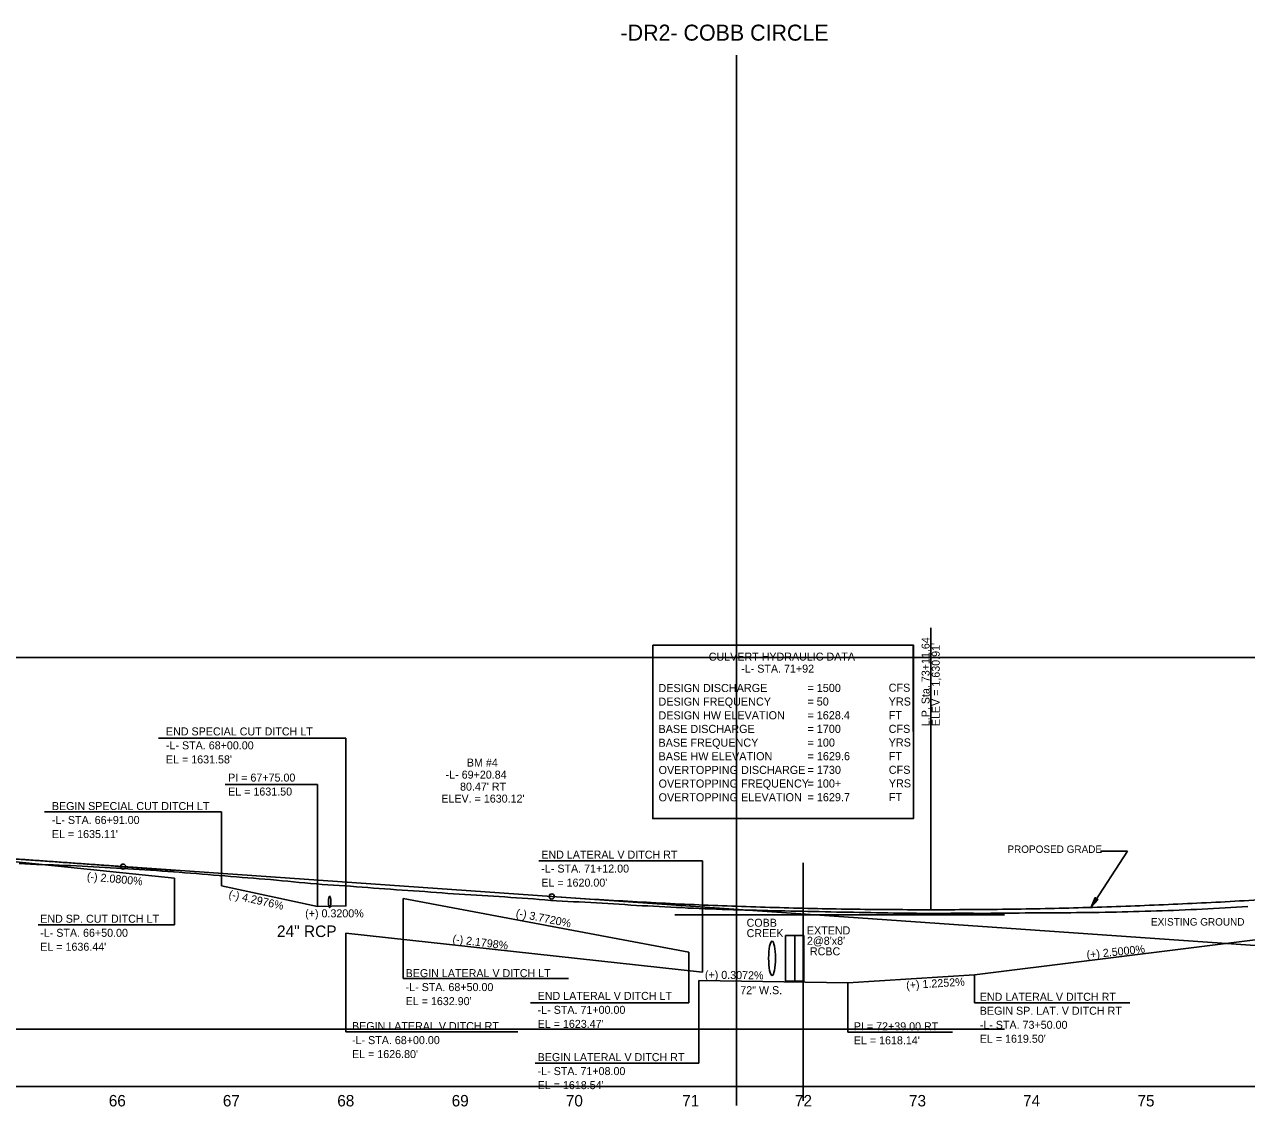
# Model space of a CAD drawing. Extents: x 498575 to 532350, y 405181 to 484585.
# Drawn here: x 511338 to 512407, y 483216 to 484163 of the extents above; entities that cross this region are included whole.
import ezdxf

# ---------------------------------------------------------------- set-up
doc = ezdxf.new("R2010")
doc.units = 0
for name, color, linetype in [('Default', 7, 'Continuous'), ('Exist Profile Cell', 7, 'Continuous'), ('Exist Structure Major Box Culvert or Tunnel Topo', 7, 'Continuous'), ('Exist Vertical Profile Ground Line', 7, 'Continuous'), ('Exist Vertical Profile Horizontal Axis Label Major', 7, 'Continuous'), ('Prop Drainage Structure Pipe RCP 60in Class III', 7, 'Continuous'), ('Prop Drainage Structure Pipe Welded Steel 54in Label', 7, 'Continuous'), ('Prop Grid Mask', 7, 'Continuous'), ('Prop PFL Text', 7, 'Continuous'), ('Prop Vertical Profile Curve Label', 7, 'Continuous'), ('Prop Vertical Profile Ditch Grade Left', 7, 'Continuous'), ('Prop Vertical Profile Ditch Grade Left Label', 7, 'Continuous'), ('Prop Vertical Profile Ditch Grade Right', 7, 'Continuous'), ('Prop Vertical Profile Ditch Grade Right Label', 7, 'Continuous'), ('Prop Vertical Profile Grade', 7, 'Continuous'), ('Prop Vertical Profile Strip Grade', 7, 'Continuous'), ('Prop VPI Label', 7, 'Continuous'), ('Scratch_Level_2', 7, 'Continuous'), ('Scratch_Level_4', 7, 'Continuous'), ('Scratch_Level_5', 7, 'Continuous'), ('Scratch_Level_8', 7, 'Continuous')]:
    doc.layers.add(name, color=color, linetype=linetype)

msp = doc.modelspace()

# ---------------------------------------------------------------- linework, layer by layer
at = {"layer": 'Exist Profile Cell'}
msp.add_line((505856.7, 483233.7), (526056.7, 483233.7), dxfattribs=at)
at = {"layer": 'Exist Structure Major Box Culvert or Tunnel Topo'}
for p, q in [((512003.7, 483325.7), (512003.7, 483365.7)), ((512011.7, 483325.7), (512011.7, 483365.7)), ((512019.7, 483325.7), (512019.7, 483365.7)), ((512003.7, 483325.7), (512011.7, 483325.7)), ((512011.7, 483325.7), (512019.7, 483325.7))]:
    msp.add_line(p, q, dxfattribs=at)
msp.add_lwpolyline([(512003.7, 483365.7), (512019.7, 483365.7)], dxfattribs=at)
at = {"layer": 'Exist Vertical Profile Ground Line'}
for points in [[(511333.2, 483428.7), (511338.2, 483428.4), (511343.2, 483428.2), (511348.2, 483427.9), (511353.2, 483427.8), (511358.2, 483427.6), (511363.2, 483427.5), (511368.2, 483427.3), (511373.2, 483427.1), (511378.2, 483426.9), (511383.2, 483426.6), (511388.2, 483426.4), (511393.2, 483426.1), (511398.2, 483425.8), (511403.2, 483425.6), (511408.2, 483425.3), (511413.2, 483425), (511418.2, 483424.7), (511423.2, 483424.4), (511428.2, 483424.1), (511433.2, 483423.8), (511438.2, 483423.5), (511443.2, 483423.2), (511448.2, 483422.8), (511453.2, 483422.5), (511458.2, 483422.1), (511463.2, 483421.7), (511468.2, 483421.4), (511473.2, 483421.1), (511478.2, 483420.7), (511483.2, 483420.3), (511488.2, 483419.9), (511493.2, 483419.4), (511498.2, 483419), (511503.2, 483418.6), (511508.2, 483418.2), (511513.2, 483417.8), (511518.2, 483417.4), (511523.2, 483417), (511528.2, 483416.6), (511533.2, 483416.2), (511538.2, 483415.8), (511543.2, 483415.4), (511548.2, 483415), (511553.2, 483414.6), (511558.2, 483414.2), (511563.2, 483413.7), (511568.2, 483413.2), (511573.2, 483412.7), (511578.2, 483412.2), (511583.2, 483411.7), (511588.2, 483411.3), (511593.2, 483410.9), (511598.2, 483410.5), (511603.2, 483410.1), (511608.2, 483409.8), (511613.2, 483409.5), (511618.2, 483409.1), (511623.2, 483408.8), (511628.2, 483408.4), (511633.2, 483408), (511638.2, 483407.6), (511643.2, 483407.2), (511648.2, 483406.9), (511653.2, 483406.5), (511658.2, 483406.2), (511663.2, 483405.8), (511668.2, 483405.5), (511673.2, 483405.1), (511678.2, 483404.8), (511683.2, 483404.5), (511688.2, 483404.1), (511693.2, 483403.8), (511698.2, 483403.4), (511703.2, 483403), (511708.2, 483402.6), (511713.2, 483402.3), (511718.2, 483402), (511723.2, 483401.7), (511728.2, 483401.4), (511733.2, 483401.1), (511738.2, 483400.8), (511743.2, 483400.5), (511748.2, 483400.1), (511753.2, 483399.8), (511758.2, 483399.5), (511763.2, 483399.1), (511768.2, 483398.8), (511773.2, 483398.4), (511778.2, 483398), (511783.2, 483397.7), (511788.2, 483397.3), (511793.2, 483396.9), (511798.2, 483396.5), (511803.2, 483396.2), (511808.2, 483395.9), (511813.2, 483395.6)], [(511813.2, 483395.6), (511818.2, 483395.3), (511823.2, 483395.1), (511828.2, 483394.9), (511833.2, 483394.6), (511838.2, 483394.3), (511843.2, 483394), (511848.2, 483393.7), (511853.2, 483393.4), (511858.2, 483393.1), (511863.2, 483392.8), (511868.2, 483392.4), (511873.2, 483392.1), (511878.2, 483391.8), (511883.2, 483391.6), (511888.2, 483391.3), (511893.2, 483391.1), (511898.2, 483390.8), (511903.2, 483390.6), (511908.2, 483390.3), (511913.2, 483390.1), (511918.2, 483389.8), (511923.2, 483389.6), (511928.2, 483389.4), (511933.2, 483389.2), (511938.2, 483389), (511943.2, 483388.8), (511948.2, 483388.6), (511953.2, 483388.4), (511958.2, 483388.3), (511963.2, 483388.2), (511968.2, 483388), (511973.2, 483387.9), (511978.2, 483387.8), (511983.2, 483387.7), (511988.2, 483387.5), (511993.2, 483387.4), (511998.2, 483387.3), (512003.2, 483387.2), (512008.2, 483387.1), (512013.2, 483387), (512018.2, 483386.9), (512023.2, 483386.8), (512028.2, 483386.7), (512033.2, 483386.6), (512038.2, 483386.5), (512043.2, 483386.4), (512048.2, 483386.3), (512053.2, 483386.3), (512058.2, 483386.2), (512063.2, 483386.1), (512068.2, 483386), (512073.2, 483385.9), (512078.2, 483385.8), (512083.2, 483385.7), (512088.2, 483385.6), (512093.2, 483385.5), (512098.2, 483385.4), (512103.2, 483385.4), (512108.2, 483385.3), (512113.2, 483385.2), (512118.2, 483385.2), (512123.2, 483385.1), (512128.2, 483385.1), (512133.2, 483385.1), (512138.2, 483385.1), (512143.2, 483385.1), (512148.2, 483385.2), (512153.2, 483385.2), (512158.2, 483385.2), (512163.2, 483385.2), (512168.2, 483385.2), (512173.2, 483385.1), (512178.2, 483385.1), (512183.2, 483385.2), (512188.2, 483385.2), (512193.2, 483385.2), (512198.2, 483385.2), (512203.2, 483385.4), (512208.2, 483385.4), (512213.2, 483385.5), (512218.2, 483385.5), (512223.2, 483385.6), (512228.2, 483385.6), (512233.2, 483385.7), (512238.2, 483385.7), (512243.2, 483385.7), (512248.2, 483385.7), (512253.2, 483385.7), (512258.2, 483385.8), (512263.2, 483385.8), (512268.2, 483385.9), (512273.2, 483385.9), (512278.2, 483386), (512283.2, 483386.1), (512288.2, 483386.2), (512293.2, 483386.3), (512298.2, 483386.4), (512303.2, 483386.5), (512308.2, 483386.7), (512313.2, 483386.8)], [(512313.2, 483386.8), (512318.2, 483387), (512323.2, 483387.1), (512328.2, 483387.3), (512333.2, 483387.4), (512338.2, 483387.6), (512343.2, 483387.7), (512348.2, 483387.9), (512353.2, 483388.1), (512358.2, 483388.4), (512363.2, 483388.6), (512368.2, 483388.8), (512373.2, 483389.1), (512378.2, 483389.4), (512383.2, 483389.7), (512388.2, 483390), (512393.2, 483390.3), (512398.2, 483390.6), (512403.2, 483390.9), (512408.2, 483391.1)]]:
    msp.add_lwpolyline(points, dxfattribs=at)
at = {"layer": 'Prop Drainage Structure Pipe RCP 60in Class III'}
msp.add_ellipse((511991.9, 483345.8), major_axis=(0, 15), ratio=0.2, dxfattribs=at)
at = {"layer": 'Prop Drainage Structure Pipe Welded Steel 54in Label'}
msp.add_ellipse((511604.8, 483395.2), major_axis=(0, 5), ratio=0.2, dxfattribs=at)
at = {"layer": 'Prop Grid Mask'}
for points in [[(511887.6, 483619.9), (512115.5, 483619.9), (512115.5, 483468), (511887.6, 483468)], [(511887.7, 483467.9), (512115.5, 483468), (512115.4, 483619.9), (511887.6, 483619.7)]]:
    msp.add_lwpolyline(points, close=True, dxfattribs=at)
at = {"layer": 'Prop PFL Text'}
for p, q in [((512271.2, 483390.4), (512302.8, 483439.5)), ((512302.8, 483439.5), (512279.3, 483439.5))]:
    msp.add_line(p, q, dxfattribs=at)
msp.add_lwpolyline([(512277.3, 483397.1), (512271.2, 483390.4), (512274.7, 483398.9), (512275.4, 483397)], close=True, dxfattribs=at)
at = {"layer": 'Prop Vertical Profile Curve Label'}
for centre in [(511424.1, 483426), (511799.1, 483399.9)]:
    msp.add_circle(centre, 2.25, dxfattribs=at)
at = {"layer": 'Prop Vertical Profile Ditch Grade Left'}
for points in [[(511169.1, 483437.2), (511319.1, 483431.5), (511469.1, 483415.9), (511469.1, 483415.9)], [(511510.1, 483409.3), (511594.1, 483391.2), (511619.1, 483391.6), (511619.1, 483391.6)], [(511669.1, 483398.2), (511919.1, 483351.1), (511919.1, 483351.1)]]:
    msp.add_lwpolyline(points, dxfattribs=at)
at = {"layer": 'Prop Vertical Profile Ditch Grade Left Label'}
for p, q in [((511455.2, 483538.3), (511619.1, 483538.3)), ((511619.1, 483538.3), (511619.1, 483391.6)), ((511513.4, 483497.9), (511594.1, 483497.9)), ((511594.1, 483497.9), (511594.1, 483391.2)), ((511355.3, 483473.9), (511510.1, 483473.9)), ((511510.1, 483473.9), (511510.1, 483409.3)), ((511469.1, 483415.9), (511469.1, 483375)), ((511669.1, 483398.2), (511669.1, 483328)), ((511349.7, 483375), (511469.1, 483375)), ((511919.1, 483351.1), (511919.1, 483306.9)), ((511669.1, 483328), (511813.9, 483328)), ((511780.4, 483306.9), (511919.1, 483306.9))]:
    msp.add_line(p, q, dxfattribs=at)
at = {"layer": 'Prop Vertical Profile Ditch Grade Right'}
for points in [[(511927.9, 483326.4), (512058.1, 483324.4), (512169.1, 483331.2), (512569.1, 483381.2)], [(511619.1, 483367.7), (511931.1, 483333.7)]]:
    msp.add_lwpolyline(points, dxfattribs=at)
at = {"layer": 'Prop Vertical Profile Ditch Grade Right Label'}
for p, q in [((511931.1, 483431), (511787.9, 483431)), ((511931.1, 483333.7), (511931.1, 483431)), ((511619.1, 483367.7), (511619.1, 483281.4)), ((512169.1, 483331.2), (512169.1, 483306.9)), ((511927.9, 483326.4), (511927.9, 483253.9)), ((512058.1, 483324.4), (512058.1, 483281.2)), ((512304.9, 483306.9), (512169.1, 483306.9)), ((511769.5, 483281.4), (511619.1, 483281.4)), ((512149.7, 483281.2), (512058.1, 483281.2)), ((511927.9, 483253.9), (511784.7, 483253.9))]:
    msp.add_line(p, q, dxfattribs=at)
at = {"layer": 'Prop Vertical Profile Grade'}
msp.add_line((511424.1, 483426), (511799.1, 483399.9), dxfattribs=at)
for points in [[(511799.1, 483399.9), (511832.3, 483397.6), (511865.5, 483395.7), (511898.7, 483393.9), (511931.9, 483392.4), (511965.1, 483391.2), (511998.3, 483390.1), (512031.5, 483389.3), (512064.7, 483388.7), (512097.9, 483388.4), (512131.1, 483388.3), (512164.3, 483388.4), (512197.5, 483388.7), (512230.7, 483389.3), (512263.9, 483390.1), (512297.1, 483391.2), (512330.3, 483392.5), (512363.5, 483394), (512396.7, 483395.7), (512429.9, 483397.7), (512463.1, 483399.9), (512496.3, 483402.3), (512529.5, 483405), (512562.7, 483407.9), (512595.9, 483411), (512629.1, 483414.4), (512662.3, 483418), (512695.5, 483421.8), (512728.7, 483425.9), (512761.9, 483430.2), (512795.1, 483434.7), (512828.3, 483439.5), (512861.5, 483444.5), (512894.7, 483449.7), (512927.9, 483455.2), (512961.1, 483460.8), (512994.3, 483466.8), (513027.5, 483472.9), (513060.7, 483479.3), (513093.9, 483485.9), (513127.1, 483492.8), (513160.3, 483499.8), (513193.5, 483507.1), (513226.7, 483514.7), (513259.9, 483522.5), (513293.1, 483530.5), (513326.3, 483538.7), (513359.5, 483547.2), (513392.7, 483555.9), (513425.9, 483564.8), (513459.1, 483574)], [(510724.1, 483483.2), (510738.1, 483481.9), (510752.1, 483480.6), (510766.1, 483479.3), (510780.1, 483478), (510794.1, 483476.8), (510808.1, 483475.5), (510822.1, 483474.2), (510836.1, 483473), (510850.1, 483471.7), (510864.1, 483470.5), (510878.1, 483469.2), (510892.1, 483468), (510906.1, 483466.8), (510920.1, 483465.5), (510934.1, 483464.3), (510948.1, 483463.1), (510962.1, 483461.9), (510976.1, 483460.7), (510990.1, 483459.5), (511004.1, 483458.4), (511018.1, 483457.2), (511032.1, 483456), (511046.1, 483454.8), (511060.1, 483453.7), (511074.1, 483452.5), (511088.1, 483451.4), (511102.1, 483450.3), (511116.1, 483449.1), (511130.1, 483448), (511144.1, 483446.9), (511158.1, 483445.8), (511172.1, 483444.7), (511186.1, 483443.6), (511200.1, 483442.5), (511214.1, 483441.4), (511228.1, 483440.4), (511242.1, 483439.3), (511256.1, 483438.2), (511270.1, 483437.2), (511284.1, 483436.1), (511298.1, 483435.1), (511312.1, 483434.1), (511326.1, 483433), (511340.1, 483432), (511354.1, 483431), (511368.1, 483430), (511382.1, 483429), (511396.1, 483428), (511410.1, 483427), (511424.1, 483426)]]:
    msp.add_spline(points, degree=3, dxfattribs=at)
at = {"layer": 'Prop Vertical Profile Strip Grade'}
msp.add_line((512130.7, 483635), (512130.7, 483388.3), dxfattribs=at)
at = {"layer": 'Prop VPI Label'}
for p, q in [((511424.1, 483426), (511076.8, 483450.3)), ((511799.1, 483399.9), (512626.3, 483342.1))]:
    msp.add_line(p, q, dxfattribs=at)
at = {"layer": 'Scratch_Level_2'}
msp.add_line((511960.7, 484136), (511960.7, 483216.9), dxfattribs=at)
at = {"layer": 'Scratch_Level_4'}
for p, q in [((512019.1, 483221.2), (512019.1, 483429.2)), ((511906.7, 483383.7), (512195.1, 483383.7)), ((512019.1, 483320.4), (512019.1, 483233.7)), ((505856.7, 483283.7), (512195.1, 483283.7)), ((511906.7, 483233.7), (512195.1, 483233.7))]:
    msp.add_line(p, q, dxfattribs=at)
at = {"layer": 'Scratch_Level_5'}
msp.add_line((513582.6, 483609), (498575.1, 483609), dxfattribs=at)
at = {"layer": 'Scratch_Level_8'}
msp.add_line((511469.1, 483422.6), (511419.1, 483426), dxfattribs=at)

# ---------------------------------------------------------------- texts
at = {"layer": 'Default'}
for s, height, p in [('CULVERT HYDRAULIC DATA', 7, (511936.5, 483606.2)), ('-L- STA. 71+92', 7, (511964.9, 483595.7)), ('DESIGN DISCHARGE', 7.087, (511892.5, 483578.7)), ('DESIGN DISCHARGE', 7.087, (511892.5, 483578.7)), ('= 1500', 7.09, (512022.8, 483578.8)), ('CFS', 7.09, (512093.9, 483579)), ('DESIGN FREQUENCY', 7.087, (511892.5, 483566.8)), ('DESIGN FREQUENCY', 7.087, (511892.5, 483566.8)), ('= 50', 7.09, (512022.8, 483566.9)), ('YRS', 7.09, (512093.9, 483566.9)), ('DESIGN HW ELEVATION', 7.087, (511892.5, 483554.8)), ('DESIGN HW ELEVATION', 7.087, (511892.5, 483554.8)), ('= 1628.4', 7.09, (512022.8, 483554.9)), ('FT', 7.09, (512093.9, 483555)), ('BASE DISCHARGE', 7.087, (511892.5, 483542.9)), ('BASE DISCHARGE', 7.087, (511892.5, 483542.9)), ('= 1700', 7.09, (512022.8, 483543)), ('CFS', 7.09, (512093.9, 483543)), ('BASE FREQUENCY', 7.087, (511892.5, 483530.9)), ('BASE FREQUENCY', 7.087, (511892.5, 483530.9)), ('= 100', 7.09, (512022.9, 483531)), ('YRS', 7.09, (512093.9, 483531.1)), ('BASE HW ELEVATION', 7.087, (511892.6, 483519)), ('BASE HW ELEVATION', 7.087, (511892.6, 483519)), ('= 1629.6', 7.09, (512022.9, 483519.1)), ('FT', 7.09, (512093.9, 483519.1)), ('OVERTOPPING DISCHARGE', 7.087, (511892.6, 483507)), ('= 1730', 7.09, (512022.9, 483507.1)), ('CFS', 7.09, (512094, 483507.2)), ('OVERTOPPING FREQUENCY', 7.087, (511892.6, 483495.1)), ('= 100+', 7.09, (512022.9, 483495.2)), ('YRS', 7.09, (512094, 483495.3)), ('OVERTOPPING ELEVATION', 7.087, (511892.6, 483483.1)), ('= 1629.7', 7.09, (512022.9, 483483.2)), ('FT', 7.09, (512094, 483483.3))]:
    msp.add_text(s, height=height, rotation=0.0449, dxfattribs=at).set_placement(p)
for s, p in [('COBB ', (511969.6, 483373.4)), ('EXTEND', (512022.4, 483366.7)), ('CREEK', (511969.6, 483364.3)), ("2@8'x8' ", (512022.4, 483357.6)), (' RCBC', (512022.4, 483348.4)), ('72" W.S.', (511964.1, 483314.4))]:
    msp.add_text(s, height=7, dxfattribs=at).set_placement(p)
at = {"layer": 'Exist Vertical Profile Horizontal Axis Label Major'}
for s, p in [('66', (511411.6, 483216.2)), ('66', (511411.6, 483216.2)), ('67', (511511.4, 483216.2)), ('67', (511511.4, 483216.2)), ('68', (511611.5, 483216.2)), ('68', (511611.5, 483216.2)), ('69', (511711.6, 483216.2)), ('69', (511711.6, 483216.2)), ('70', (511811.5, 483216.2)), ('70', (511811.5, 483216.2)), ('71', (511913.3, 483216.2)), ('71', (511913.3, 483216.2)), ('72', (512011.9, 483216.2)), ('72', (512011.9, 483216.2)), ('73', (512111.7, 483216.2)), ('73', (512111.7, 483216.2)), ('74', (512211.5, 483216.2)), ('74', (512211.5, 483216.2)), ('75', (512311.6, 483216.2)), ('75', (512311.6, 483216.2))]:
    msp.add_text(s, height=10, dxfattribs=at).set_placement(p)
at = {"layer": 'Prop Drainage Structure Pipe Welded Steel 54in Label'}
msp.add_text('24" RCP', height=10.12, dxfattribs=at).set_placement((511558.7, 483364.4))
at = {"layer": 'Prop PFL Text'}
for s, height, p in [('BM #4', 7, (511724.9, 483513.5)), ('-L- 69+20.84', 7, (511706.3, 483503)), ("80.47' RT", 7, (511718.9, 483492.5)), ("ELEV. = 1630.12'", 7, (511702.5, 483482)), ('PROPOSED GRADE', 6.516, (512197.8, 483438)), ('EXISTING GROUND', 6.516, (512323.4, 483374.4))]:
    msp.add_text(s, height=height, dxfattribs=at).set_placement(p)
at = {"layer": 'Prop Vertical Profile Ditch Grade Left Label'}
for s, rotation, p in [('END SPECIAL CUT DITCH LT', 360, (511461.6, 483540.8)), ('-L- STA. 68+00.00', 360, (511461.6, 483528.6)), ("EL = 1631.58'", 360, (511461.6, 483516.3)), ('PI = 67+75.00', 360, (511516, 483500.4)), ('EL = 1631.50', 360, (511516, 483488.2)), ('BEGIN SPECIAL CUT DITCH LT', 360, (511361.8, 483475.5)), ('-L- STA. 66+91.00', 360, (511361.8, 483463.3)), ("EL = 1635.11'", 360, (511361.8, 483451)), ('(-) 2.0800%', 354.7041, (511392.2, 483414.1)), ('(-) 4.2976%', 347.3995, (511516, 483398.8)), ('END SP. CUT DITCH LT', 360, (511351.6, 483376.9)), ('(+) 0.3200%', 0.0204, (511583.4, 483381.6)), ('(-) 3.7720%', 348.7075, (511767.3, 483382.3)), ('-L- STA. 66+50.00', 360, (511351.6, 483364.6)), ("EL = 1636.44'", 360, (511351.6, 483352.4)), ('BEGIN LATERAL V DITCH LT', 360, (511671.3, 483329.3)), ('-L- STA. 68+50.00', 360, (511671.3, 483317.1)), ("EL = 1632.90'", 360, (511671.3, 483304.8)), ('END LATERAL V DITCH LT', 360, (511786.8, 483309.4)), ('-L- STA. 71+00.00', 360, (511786.8, 483297.2)), ("EL = 1623.47'", 360, (511786.8, 483284.9))]:
    msp.add_text(s, height=7, rotation=rotation, dxfattribs=at).set_placement(p)
at = {"layer": 'Prop Vertical Profile Ditch Grade Right Label'}
for s, rotation, p in [('END LATERAL V DITCH RT', 360, (511790, 483433)), ('-L- STA. 71+12.00', 360, (511790, 483420.8)), ("EL = 1620.00'", 360, (511790, 483408.5)), ('(-) 2.1798%', 352.9061, (511712, 483359.4)), ('(+) 2.5000%', 5.8692, (512267.4, 483345.4)), ('(+) 0.3072%', 359.2391, (511933.1, 483328)), ('(+) 1.2252%', 3.4628, (512109.4, 483318.8)), ('END LATERAL V DITCH RT', 360, (512173.6, 483308.6)), ('BEGIN SP. LAT. V DITCH RT', 360, (512173.6, 483296.4)), ('BEGIN LATERAL V DITCH RT', 360, (511624.4, 483283)), ('PI = 72+39.00 RT', 360, (512063.4, 483282.8)), ('-L- STA. 73+50.00', 360, (512173.6, 483284.1)), ('-L- STA. 68+00.00', 360, (511624.4, 483270.7)), ("EL = 1618.14'", 360, (512063.4, 483270.5)), ("EL = 1619.50'", 360, (512173.6, 483271.9)), ("EL = 1626.80'", 360, (511624.4, 483258.5)), ('BEGIN LATERAL V DITCH RT', 360, (511786.8, 483255.8)), ('-L- STA. 71+08.00', 360, (511786.8, 483243.6)), ("EL = 1618.54'", 360, (511786.8, 483231.3))]:
    msp.add_text(s, height=7, rotation=rotation, dxfattribs=at).set_placement(p)
at = {"layer": 'Prop Vertical Profile Strip Grade'}
for s, p in [('L.P. Sta. 73+11.64', (512129.7, 483548.9)), ("ELEV = 1,630.91'", (512138.6, 483548.9))]:
    msp.add_text(s, height=7, rotation=90, dxfattribs=at).set_placement(p)
at = {"layer": 'Scratch_Level_2'}
msp.add_text('-DR2- COBB CIRCLE', height=14, dxfattribs=at).set_placement((511859.3, 484148.7))

doc.saveas('drawing.dxf')
